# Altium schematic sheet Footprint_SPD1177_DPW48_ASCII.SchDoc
size A4; 项目编号: SPSZ2023-052501A; 项目名称: 三相PFC-2.2KW压机+700W风机
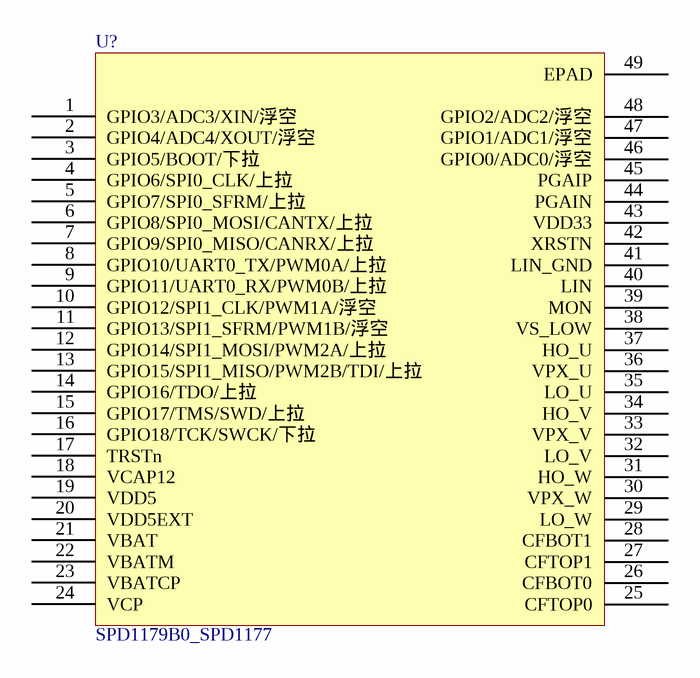
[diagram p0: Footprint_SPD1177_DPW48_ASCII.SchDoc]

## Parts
U?  SPD1179B0_SPD1177  [QFN48-0.5-1179-QFN50P700X700X90_HS-49M]

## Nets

Not connected (* = marked no-connect by the designer): U? 1(GPIO3/ADC3/XIN/浮空) 2(GPIO4/ADC4/XOUT/浮空) 3(GPIO5/BOOT/下拉) 4(GPIO6/SPI0_CLK/上拉) 5(GPIO7/SPI0_SFRM/上拉) 6(GPIO8/SPI0_MOSI/CANTX/上拉) 7(GPIO9/SPI0_MISO/CANRX/上拉) 8(GPIO10/UART0_TX/PWM0A/上拉) 9(GPIO11/UART0_RX/PWM0B/上拉) 10(GPIO12/SPI1_CLK/PWM1A/浮空) 11(GPIO13/SPI1_SFRM/PWM1B/浮空) 12(GPIO14/SPI1_MOSI/PWM2A/上拉) 13(GPIO15/SPI1_MISO/PWM2B/TDI/上拉) 14(GPIO16/TDO/上拉) 15(GPIO17/TMS/SWD/上拉) 16(GPIO18/TCK/SWCK/下拉) 17(TRSTn) 18(VCAP12) 19(VDD5) 20(VDD5EXT) 21(VBAT) 22(VBATM) 23(VBATCP) 24(VCP) 25(CFTOP0) 26(CFBOT0) 27(CFTOP1) 28(CFBOT1) 29(LO_W) 30(VPX_W) 31(HO_W) 32(LO_V) 33(VPX_V) 34(HO_V) 35(LO_U) 36(VPX_U) 37(HO_U) 38(VS_LOW) 39(MON) 40(LIN) 41(LIN_GND) 42(XRSTN) 43(VDD33) 44(PGAIN) 45(PGAIP) 46(GPIO0/ADC0/浮空) 47(GPIO1/ADC1/浮空) 48(GPIO2/ADC2/浮空) 49(EPAD)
